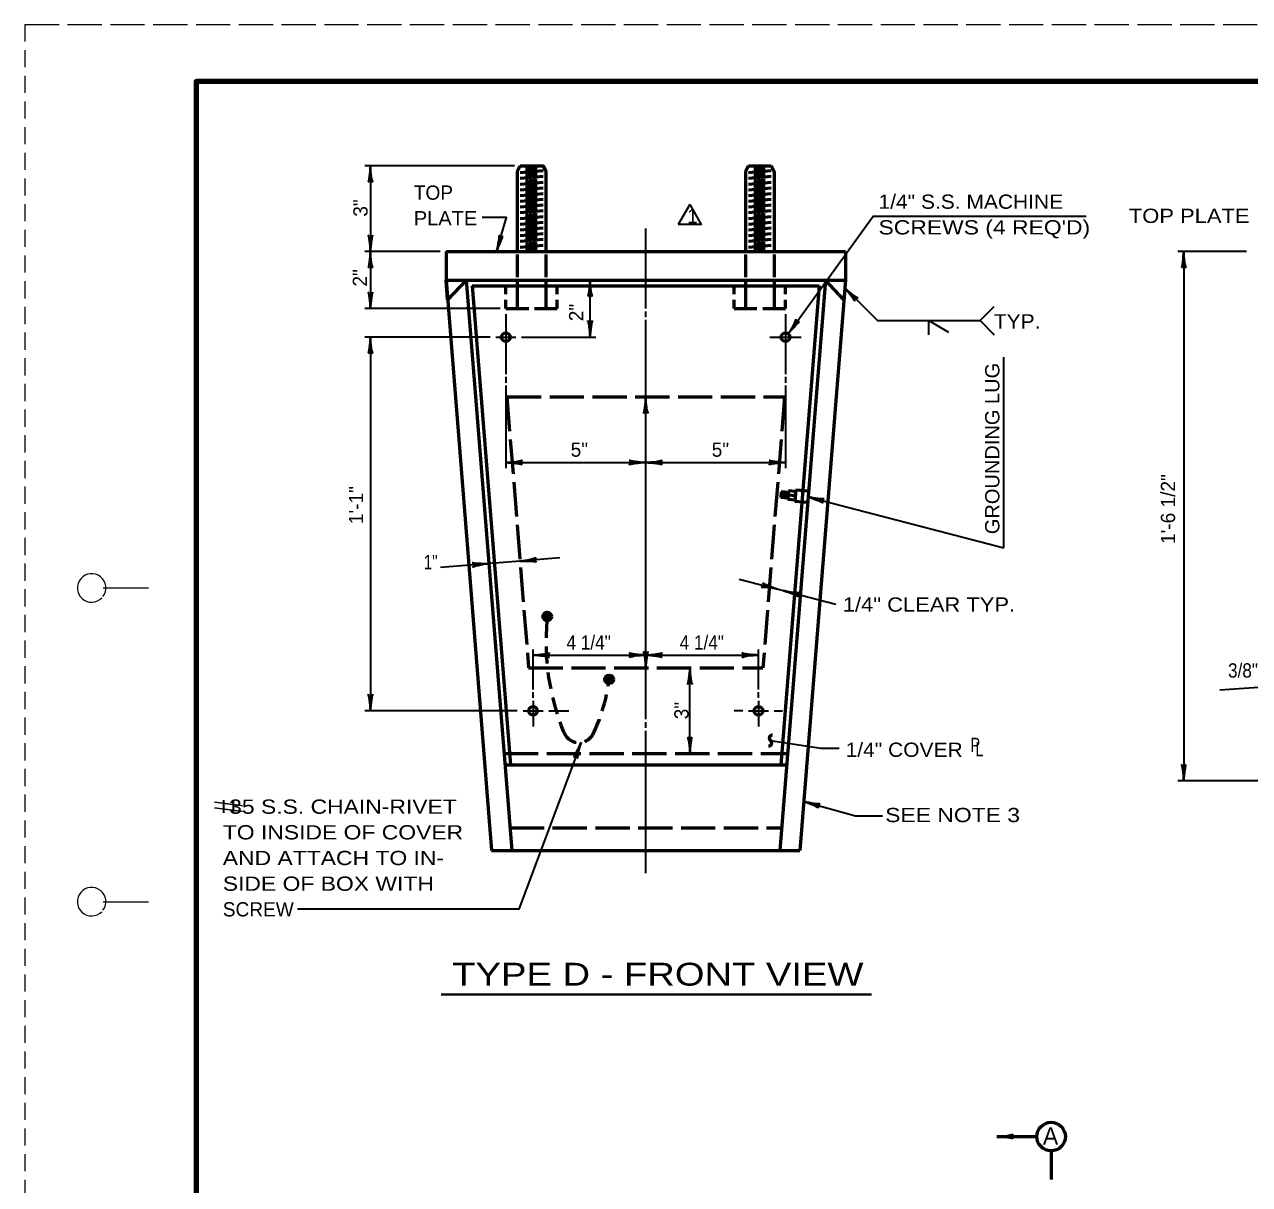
# Model space of a CAD drawing. Extents: x -1 to 679, y 0 to 440.
# Drawn here: x -1.1 to 213.6, y 236.4 to 439.8 of the extents above; entities that cross this region are included whole.
import ezdxf

# ---------------------------------------------------------------- set-up
doc = ezdxf.new("R2010")
doc.units = 0
doc.linetypes.add('LONG_DASHED', pattern=[7.5, 6, -1.5])
doc.linetypes.add('MEDIUM_DASHED', pattern=[4.5, 3, -1.5])
doc.layers.add('1', color=7, linetype='Continuous', lineweight=35)
doc.layers.add('61', color=7, linetype='Continuous', lineweight=35)

msp = doc.modelspace()

# ---------------------------------------------------------------- hatches: boundary and pattern name
at = {"layer": '1'}
for points in [[(91.319, 335.992, 1), (89.819, 335.992, 1)], [(102.185, 324.992, 1), (100.685, 324.992, 1)]]:
    msp.add_hatch(color=256, dxfattribs=at).paths.add_polyline_path(points)

# ---------------------------------------------------------------- linework, layer by layer
at = {"layer": '1', "linetype": 'MEDIUM_DASHED', "lineweight": 13}
msp.add_line((-0.995, 439.78), (-1.055, -0.26), dxfattribs=at)
at = {"layer": '1'}
for p, q in [((84.82, 414.992), (58.57, 414.992)), ((115.531, 408.207), (113.531, 404.743)), ((107.82, 389.992), (107.82, 403.992)), ((71.82, 399.992), (58.57, 399.992)), ((213.108, 399.992), (201.108, 399.992)), ((202.108, 399.992), (202.108, 307.218)), ((98.07, 384.992), (98.07, 394.992)), ((82.32, 389.992), (58.57, 389.992)), ((83.32, 388.992), (83.32, 378.492)), ((107.82, 388.492), (107.82, 389.492)), ((132.321, 388.992), (132.321, 378.492)), ((107.82, 374.492), (107.82, 387.992)), ((166.43, 387.873), (168.905, 385.398)), ((80.57, 384.992), (58.57, 384.992)), ((59.57, 384.992), (59.57, 319.492)), ((86.07, 384.992), (99.07, 384.992)), ((129.571, 384.992), (135.07, 384.992)), ((170.607, 348.058), (170.607, 381.474)), ((83.32, 377.992), (83.32, 376.992)), ((132.321, 377.992), (132.321, 376.992)), ((83.32, 376.492), (83.32, 361.992)), ((132.321, 376.492), (132.321, 361.992)), ((136.216, 357), (170.607, 348.058)), ((88.07, 323.242), (88.07, 330.242)), ((127.57, 323.242), (127.57, 330.242)), ((115.57, 311.992), (115.57, 326.992)), ((88.07, 321.742), (88.07, 322.742)), ((127.57, 321.742), (127.57, 322.742)), ((208.456, 323.135), (219.429, 323.902)), ((88.07, 321.242), (88.07, 316.742)), ((127.57, 321.242), (127.57, 316.742)), ((85.32, 319.492), (58.57, 319.492)), ((86.32, 319.492), (89.82, 319.492)), ((90.82, 319.492), (94.32, 319.492)), ((124.82, 319.492), (123.32, 319.492)), ((125.82, 319.492), (129.321, 319.492)), ((130.321, 319.492), (131.821, 319.492)), ((107.82, 316.492), (107.82, 317.492)), ((107.82, 290.992), (107.82, 315.992)), ((219.596, 307.218), (201.108, 307.218))]:
    msp.add_line(p, q, dxfattribs=at)
at = {"layer": '1', "lineweight": 53}
for p, q in [((85.82, 414.992), (85.32, 413.992)), ((86.773, 414.411), (88.781, 414.587)), ((125.82, 414.992), (125.32, 413.992)), ((125.82, 414.992), (129.821, 414.992)), ((126.773, 414.411), (128.781, 414.587)), ((129.821, 414.992), (130.321, 413.992)), ((85.32, 413.992), (85.32, 399.992)), ((85.82, 413.826), (89.82, 414.176)), ((85.82, 412.822), (89.82, 413.172)), ((86.773, 413.408), (88.781, 413.583)), ((86.773, 412.404), (88.781, 412.579)), ((90.32, 413.992), (90.32, 399.992)), ((125.32, 413.992), (125.32, 399.992)), ((125.82, 413.826), (129.821, 414.176)), ((125.82, 412.822), (129.821, 413.172)), ((126.773, 413.408), (128.781, 413.583)), ((126.773, 412.404), (128.781, 412.579)), ((130.321, 413.992), (130.321, 399.992)), ((85.82, 411.819), (89.82, 412.169)), ((85.82, 410.815), (89.82, 411.165)), ((85.82, 409.811), (89.82, 410.161)), ((86.773, 411.4), (88.781, 411.576)), ((86.773, 410.396), (88.781, 410.572)), ((125.82, 411.819), (129.821, 412.169)), ((125.82, 410.815), (129.821, 411.165)), ((125.82, 409.811), (129.821, 410.161)), ((126.773, 411.4), (128.781, 411.576)), ((126.773, 410.396), (128.781, 410.572)), ((85.82, 408.807), (89.82, 409.157)), ((85.82, 407.803), (89.82, 408.153)), ((86.773, 409.392), (88.781, 409.568)), ((86.773, 408.388), (88.781, 408.564)), ((125.82, 408.807), (129.821, 409.157)), ((125.82, 407.803), (129.821, 408.153)), ((126.773, 409.392), (128.781, 409.568)), ((126.773, 408.388), (128.781, 408.564)), ((85.82, 406.799), (89.82, 407.149)), ((85.82, 405.796), (89.82, 406.146)), ((86.773, 407.385), (88.781, 407.56)), ((86.773, 406.381), (88.781, 406.557)), ((125.82, 406.799), (129.821, 407.149)), ((125.82, 405.796), (129.821, 406.146)), ((126.773, 407.385), (128.781, 407.56)), ((126.773, 406.381), (128.781, 406.557)), ((85.82, 404.792), (89.82, 405.142)), ((85.82, 403.788), (89.82, 404.138)), ((86.773, 405.377), (88.781, 405.553)), ((86.773, 404.373), (88.781, 404.549)), ((125.82, 404.792), (129.821, 405.142)), ((125.82, 403.788), (129.821, 404.138)), ((126.773, 405.377), (128.781, 405.553)), ((126.773, 404.373), (128.781, 404.549)), ((85.82, 402.784), (89.82, 403.134)), ((85.82, 401.78), (89.82, 402.13)), ((86.773, 403.369), (88.781, 403.545)), ((86.773, 402.365), (88.781, 402.541)), ((86.773, 401.362), (88.781, 401.537)), ((125.82, 402.784), (129.821, 403.134)), ((125.82, 401.78), (129.821, 402.13)), ((126.773, 403.369), (128.781, 403.545)), ((126.773, 402.365), (128.781, 402.541)), ((126.773, 401.362), (128.781, 401.537)), ((72.82, 399.992), (142.82, 399.992)), ((72.82, 399.992), (72.82, 394.992)), ((85.32, 399.492), (85.32, 395.492)), ((85.82, 400.777), (89.82, 401.126)), ((86.773, 400.358), (88.781, 400.534)), ((90.32, 399.492), (90.32, 395.492)), ((125.32, 399.492), (125.32, 395.492)), ((125.82, 400.777), (129.821, 401.126)), ((126.773, 400.358), (128.781, 400.534)), ((130.321, 399.492), (130.321, 395.492)), ((142.82, 399.992), (142.82, 394.992)), ((72.82, 394.992), (142.82, 394.992)), ((72.821, 394.992), (80.82, 294.992)), ((76.332, 394.992), (84.332, 294.992)), ((77.415, 393.992), (84.135, 309.992)), ((77.415, 393.992), (138.226, 393.992)), ((83.32, 392.492), (83.32, 393.992)), ((85.32, 394.992), (85.32, 389.992)), ((90.32, 394.992), (90.32, 389.992)), ((92.32, 392.492), (92.32, 393.992)), ((123.32, 392.492), (123.32, 393.992)), ((125.32, 394.992), (125.32, 389.992)), ((130.321, 394.992), (130.321, 389.992)), ((139.309, 394.992), (131.309, 294.992)), ((138.226, 393.992), (131.506, 309.992)), ((132.321, 392.492), (132.321, 393.992)), ((142.82, 394.992), (134.82, 294.992)), ((83.32, 389.992), (83.32, 391.492)), ((92.32, 389.992), (92.32, 391.492)), ((123.32, 389.992), (123.32, 391.492)), ((132.321, 389.992), (132.321, 391.492)), ((83.32, 389.992), (87.32, 389.992)), ((88.32, 389.992), (92.32, 389.992)), ((123.32, 389.992), (127.32, 389.992)), ((128.321, 389.992), (132.321, 389.992)), ((131.575, 357.872), (131.495, 356.875)), ((132.741, 356.776), (131.495, 356.875)), ((132.82, 357.772), (131.575, 357.872)), ((131.772, 357.605), (131.732, 357.107)), ((131.988, 357.839), (131.908, 356.842)), ((132.195, 357.572), (132.155, 357.073)), ((132.4, 357.806), (132.321, 356.809)), ((132.621, 357.537), (132.581, 357.039)), ((132.84, 358.022), (132.721, 356.526)), ((133.967, 356.427), (132.721, 356.526)), ((134.027, 357.174), (132.781, 357.274)), ((134.087, 357.922), (132.84, 358.022)), ((134.106, 358.171), (133.947, 356.178)), ((136.349, 357.992), (134.106, 358.171)), ((136.19, 355.998), (133.947, 356.178)), ((83.132, 309.992), (132.509, 309.992)), ((80.82, 294.992), (134.82, 294.992)), ((169.37, 244.85), (176.37, 244.85)), ((178.87, 242.35), (178.87, 237.35))]:
    msp.add_line(p, q, dxfattribs=at)
at = {"layer": '1', "linetype": 'LONG_DASHED', "lineweight": 53}
for p, q in [((83.489, 374.492), (132.152, 374.492)), ((83.489, 374.492), (87.289, 326.992)), ((132.152, 374.492), (128.352, 326.992)), ((87.289, 326.992), (128.352, 326.992)), ((82.972, 311.992), (132.669, 311.992)), ((84.012, 298.992), (131.629, 298.992))]:
    msp.add_line(p, q, dxfattribs=at)
at = {"layer": '1', "lineweight": 40}
msp.add_line((71.944, 269.731), (147.413, 269.731), dxfattribs=at)
at = {"layer": '1'}
for points in [[(59.57, 414.992), (59.57, 399.992), (59.57, 389.992)], [(115.531, 408.207), (117.531, 404.743), (113.531, 404.743)], [(81.679, 399.992), (83.407, 405.946), (79.151, 405.946)], [(132.803, 385.566), (147.675, 406.201), (184.997, 406.201)], [(142.709, 393.595), (148.43, 387.873), (166.43, 387.873), (168.905, 390.348)], [(157.43, 385.373), (157.43, 387.873), (160.894, 385.873)], [(81.57, 384.992), (82.57, 384.992), (84.07, 384.992), (85.07, 384.992)], [(107.82, 317.992), (107.82, 326.992), (107.82, 374.492)], [(83.32, 362.992), (107.82, 362.992), (132.321, 362.992)], [(92.769, 346.268), (85.792, 345.709), (71.837, 344.593)], [(124.195, 342.56), (130.97, 340.798), (131.938, 340.547), (141.132, 338.156)], [(88.07, 329.242), (107.82, 329.242), (127.57, 329.242)], [(96.508, 313.95), (85.581, 284.709), (46.773, 284.709)], [(129.696, 314.254), (138.498, 312.907), (141.707, 312.907)], [(135.508, 303.585), (144.618, 301.093), (149.316, 301.093)]]:
    msp.add_lwpolyline(points, dxfattribs=at)
at = {"layer": '1', "lineweight": 53}
msp.add_lwpolyline([(85.82, 414.992), (89.82, 414.992), (90.32, 413.992)], dxfattribs=at)
for points in [[(73.1, 391.503), (72.82, 394.992), (76.332, 394.992), (73.1, 391.503)], [(139.309, 394.992), (142.82, 394.992), (142.541, 391.503)]]:
    msp.add_lwpolyline(points, close=True, dxfattribs=at)
for centre, radius in [((83.32, 384.992), 0.75), ((132.321, 384.992), 0.75), ((90.569, 335.992), 0.75), ((101.435, 324.992), 0.75), ((88.07, 319.492), 0.75), ((127.57, 319.492), 0.75), ((178.87, 244.85), 2.5)]:
    msp.add_circle(centre, radius, dxfattribs=at)
at = {"layer": '1', "linetype": 'MEDIUM_DASHED', "lineweight": 53}
for centre, radius, start, end in [((132.326, 331.569), 41.983, 174.97679, 202.08241), ((71.312, 328.629), 30.32, 333.87309, 351.69814), ((96.103, 316.78), 2.859, 200.36157, 328.28934)]:
    msp.add_arc(centre, radius, start, end, dxfattribs=at)
at = {"layer": '1', "lineweight": 53}
for centre, start, end in [((129.412, 313.828), 261.71531, 56.28469), ((129.981, 314.681), 81.71531, 236.28469)]:
    msp.add_arc(centre, 0.513, start, end, dxfattribs=at)
at = {"layer": '1', "lineweight": 40}
for centre, major_axis, ratio, start_param, end_param in [((59.359, 413.871), (0.176, 1.756), 0.07063, 3.1407148, 5.41811), ((59.359, 413.871), (0.176, 1.756), 0.07063, 3.1407148, 5.41811), ((59.847, 413.901), (-0.156, 1.786), 0.122415, 0.8963533, 3.1415927), ((59.847, 413.901), (-0.156, 1.786), 0.122415, 0.8963533, 3.1415927), ((59.294, 401.083), (0.156, -1.786), 0.122415, 0.8963533, 3.1415927), ((59.294, 401.083), (0.156, -1.786), 0.122415, 0.8963533, 3.1415927), ((59.782, 401.112), (-0.176, -1.756), 0.07063, 3.1407148, 5.41811), ((59.782, 401.112), (-0.176, -1.756), 0.07063, 3.1407148, 5.41811), ((81.717, 401.117), (-0.348, -1.758), 0.122415, 0.8963533, 3.1415927), ((82.194, 401.009), (0.658, 1.638), 0.07063, 6.2823074, 8.5597026), ((59.359, 398.871), (0.176, 1.756), 0.07063, 3.1407148, 5.41811), ((59.359, 398.871), (0.176, 1.756), 0.07063, 3.1407148, 5.41811), ((59.847, 398.901), (-0.156, 1.786), 0.122415, 0.8963533, 3.1415927), ((59.847, 398.901), (-0.156, 1.786), 0.122415, 0.8963533, 3.1415927), ((201.897, 398.871), (0.176, 1.756), 0.07063, 3.1407148, 5.41811), ((202.385, 398.901), (-0.156, 1.786), 0.122415, 0.8963533, 3.1415927), ((97.859, 393.871), (0.176, 1.756), 0.07063, 3.1407148, 5.41811), ((98.347, 393.901), (-0.156, 1.786), 0.122415, 0.8963533, 3.1415927), ((143.351, 392.653), (1.118, -1.366), 0.07063, 6.2823074, 8.5597026), ((143.351, 392.653), (1.118, -1.366), 0.07063, 6.2823074, 8.5597026), ((143.676, 393.019), (-1.373, 1.152), 0.122415, 0.8963533, 3.1415927), ((143.676, 393.019), (-1.373, 1.152), 0.122415, 0.8963533, 3.1415927), ((59.294, 391.083), (0.156, -1.786), 0.122415, 0.8963533, 3.1415927), ((59.294, 391.083), (0.156, -1.786), 0.122415, 0.8963533, 3.1415927), ((59.782, 391.112), (-0.176, -1.756), 0.07063, 3.1407148, 5.41811), ((59.782, 391.112), (-0.176, -1.756), 0.07063, 3.1407148, 5.41811), ((97.794, 386.083), (0.156, -1.786), 0.122415, 0.8963533, 3.1415927), ((98.282, 386.112), (-0.176, -1.756), 0.07063, 3.1407148, 5.41811), ((133.217, 386.613), (-0.917, -1.54), 0.122415, 0.8963533, 3.1415927), ((133.629, 386.352), (1.17, 1.322), 0.07063, 6.2823074, 8.5597026), ((59.359, 383.871), (0.176, 1.756), 0.07063, 3.1407148, 5.41811), ((59.847, 383.901), (-0.156, 1.786), 0.122415, 0.8963533, 3.1415927), ((107.609, 373.371), (0.176, 1.756), 0.07063, 3.1407148, 5.41811), ((108.097, 373.401), (-0.156, 1.786), 0.122415, 0.8963533, 3.1415927), ((84.441, 362.78), (-1.756, 0.176), 0.07063, 3.1407148, 5.41811), ((84.412, 363.268), (-1.786, -0.156), 0.122415, 0.8963533, 3.1415927), ((106.729, 362.715), (1.786, 0.156), 0.122415, 0.8963533, 3.1415927), ((106.729, 362.715), (1.786, 0.156), 0.122415, 0.8963533, 3.1415927), ((106.7, 363.203), (1.756, -0.176), 0.07063, 3.1407148, 5.41811), ((106.7, 363.203), (1.756, -0.176), 0.07063, 3.1407148, 5.41811), ((108.941, 362.78), (-1.756, 0.176), 0.07063, 3.1407148, 5.41811), ((108.941, 362.78), (-1.756, 0.176), 0.07063, 3.1407148, 5.41811), ((108.912, 363.268), (-1.786, -0.156), 0.122415, 0.8963533, 3.1415927), ((108.912, 363.268), (-1.786, -0.156), 0.122415, 0.8963533, 3.1415927), ((131.229, 362.715), (1.786, 0.156), 0.122415, 0.8963533, 3.1415927), ((131.2, 363.203), (1.756, -0.176), 0.07063, 3.1407148, 5.41811), ((137.247, 356.513), (-1.656, 0.612), 0.07063, 3.1407148, 5.41811), ((137.342, 356.993), (-1.768, 0.298), 0.122415, 0.8963533, 3.1415927), ((86.857, 346.072), (-1.768, -0.298), 0.122415, 0.8963533, 3.1415927), ((86.857, 346.072), (-1.768, -0.298), 0.122415, 0.8963533, 3.1415927), ((86.925, 345.588), (-1.765, 0.035), 0.07063, 3.1407148, 5.41811), ((86.925, 345.588), (-1.765, 0.035), 0.07063, 3.1407148, 5.41811), ((79.176, 345.392), (-1.765, 0.035), 0.07063, 6.2823074, 8.5597026), ((79.244, 344.908), (1.768, 0.298), 0.122415, 0.8963533, 3.1415927), ((129.939, 341.285), (-1.656, 0.612), 0.07063, 6.2823074, 8.5597026), ((129.939, 341.285), (-1.656, 0.612), 0.07063, 6.2823074, 8.5597026), ((129.845, 340.806), (1.768, -0.298), 0.122415, 0.8963533, 3.1415927), ((129.845, 340.806), (1.768, -0.298), 0.122415, 0.8963533, 3.1415927), ((132.969, 340.06), (1.656, -0.612), 0.07063, 6.2823074, 8.5597026), ((133.064, 340.54), (-1.768, 0.298), 0.122415, 0.8963533, 3.1415927), ((89.191, 329.03), (-1.756, 0.176), 0.07063, 3.1407148, 5.41811), ((89.191, 329.03), (-1.756, 0.176), 0.07063, 3.1407148, 5.41811), ((89.162, 329.518), (-1.786, -0.156), 0.122415, 0.8963533, 3.1415927), ((89.162, 329.518), (-1.786, -0.156), 0.122415, 0.8963533, 3.1415927), ((106.729, 328.965), (1.786, 0.156), 0.122415, 0.8963533, 3.1415927), ((106.7, 329.453), (1.756, -0.176), 0.07063, 3.1407148, 5.41811), ((107.544, 328.083), (0.156, -1.786), 0.122415, 0.8963533, 3.1415927), ((108.941, 329.03), (-1.756, 0.176), 0.07063, 3.1407148, 5.41811), ((108.941, 329.03), (-1.756, 0.176), 0.07063, 3.1407148, 5.41811), ((108.912, 329.518), (-1.786, -0.156), 0.122415, 0.8963533, 3.1415927), ((108.912, 329.518), (-1.786, -0.156), 0.122415, 0.8963533, 3.1415927), ((108.032, 328.112), (-0.176, -1.756), 0.07063, 3.1407148, 5.41811), ((126.479, 328.965), (1.786, 0.156), 0.122415, 0.8963533, 3.1415927), ((126.479, 328.965), (1.786, 0.156), 0.122415, 0.8963533, 3.1415927), ((126.45, 329.453), (1.756, -0.176), 0.07063, 3.1407148, 5.41811), ((126.45, 329.453), (1.756, -0.176), 0.07063, 3.1407148, 5.41811), ((115.359, 325.871), (0.176, 1.756), 0.07063, 3.1407148, 5.41811), ((115.847, 325.901), (-0.156, 1.786), 0.122415, 0.8963533, 3.1415927), ((59.294, 320.583), (0.156, -1.786), 0.122415, 0.8963533, 3.1415927), ((59.782, 320.612), (-0.176, -1.756), 0.07063, 3.1407148, 5.41811), ((95.917, 312.975), (0.779, 1.584), 0.07063, 3.1407148, 5.41811), ((96.384, 312.831), (0.479, 1.727), 0.122415, 0.8963533, 3.1415927), ((115.294, 313.083), (0.156, -1.786), 0.122415, 0.8963533, 3.1415927), ((115.782, 313.112), (-0.176, -1.756), 0.07063, 3.1407148, 5.41811), ((201.832, 308.31), (0.156, -1.786), 0.122415, 0.8963533, 3.1415927), ((202.32, 308.339), (-0.176, -1.756), 0.07063, 3.1407148, 5.41811), ((136.533, 303.085), (-1.648, 0.633), 0.07063, 3.1407148, 5.41811), ((136.533, 303.085), (-1.648, 0.633), 0.07063, 3.1407148, 5.41811), ((136.633, 303.563), (-1.764, 0.32), 0.122415, 0.8963533, 3.1415927), ((136.633, 303.563), (-1.764, 0.32), 0.122415, 0.8963533, 3.1415927), ((170.491, 244.639), (-1.756, 0.176), 0.07063, 3.1407148, 5.41811), ((170.462, 245.127), (-1.786, -0.156), 0.122415, 0.8963533, 3.1415927)]:
    msp.add_ellipse(centre, major_axis=major_axis, ratio=ratio, start_param=start_param, end_param=end_param, dxfattribs=at)
at = {"layer": '61', "linetype": 'LONG_DASHED', "lineweight": 13}
msp.add_line((-0.995, 439.78), (679.025, 439.78), dxfattribs=at)
at = {"layer": '61', "lineweight": 13}
for p, q in [((12.725, 341.02), (20.705, 341.04)), ((12.705, 286.02), (20.705, 286.02))]:
    msp.add_line(p, q, dxfattribs=at)
at = {"layer": '61', "lineweight": 158}
msp.add_lwpolyline([(668.045, 429.78), (29.005, 429.78), (29.005, 9.76)], dxfattribs=at)
at = {"layer": '61', "lineweight": 13}
for centre, end in [((10.703, 341.021), 316.23216), ((10.703, 286.021), 315.37577)]:
    msp.add_arc(centre, 2.5, 323.13009, end, dxfattribs=at)

# ---------------------------------------------------------------- texts
at = {"layer": '1'}
for s, height, p in [('TOP', 2.5, (67.177, 409.067)), ('1', 2.5, (115.079, 404.945)), ('5"', 2.5, (94.666, 364.009)), ('5"', 2.5, (119.388, 364.009)), ('SCREW', 2.5, (33.698, 283.43)), ('A', 3, (177.436, 243.457))]:
    msp.add_text(s, height=height, dxfattribs=at).set_placement(p)
for s, height, width, p in [('1/4" S.S. MACHINE', 2.5, 1.1, (148.621, 407.477)), ('PLATE', 2.5, 1.05, (67.177, 404.567)), ('TOP PLATE', 2.5, 1.15, (192.5, 404.995)), ("SCREWS (4 REQ'D)", 2.5, 1.2, (148.621, 402.977)), ('TYP.', 2.5, 1.1, (168.832, 386.491)), ('1"', 2.5, 0.8, (68.906, 344.294)), ('1/4" CLEAR TYP.', 2.5, 1.15, (142.358, 336.858)), ('4 1/4"', 2.5, 0.9, (93.937, 330.212)), ('4 1/4"', 2.5, 0.9, (113.772, 330.212)), ('3/8"', 2.5, 0.9, (209.879, 325.308)), ('1/4" COVER', 2.5, 1.1, (142.855, 311.406)), ('P', 2.5, 0.75, (164.758, 312.258)), ('L', 2.5, 0.75, (165.61, 311.527)), (' 35 S.S. CHAIN-RIVET', 2.5, 1.2, (33.698, 301.43)), ('SEE NOTE 3', 2.5, 1.2, (149.791, 299.963)), ('TO INSIDE OF COVER', 2.5, 1.2, (33.698, 296.93)), ('AND ATTACH TO IN-', 2.5, 1.2, (33.698, 292.43)), ('SIDE OF BOX WITH', 2.5, 1.2, (33.698, 287.93)), ('TYPE D - FRONT VIEW', 4, 1.25, (73.919, 271.311))]:
    msp.add_text(s, height=height, dxfattribs=dict(at, width=width)).set_placement(p)
for s, p in [('3"', (59.077, 406.089)), ('2"', (58.979, 393.843)), ('2"', (96.88, 387.769)), ('1\'-6 1/2"', (200.61, 348.723)), ('1\'-1"', (58.293, 352.207)), ('3"', (115.333, 317.992))]:
    msp.add_text(s, height=2.5, rotation=90, dxfattribs=at).set_placement(p)
for s, height, width, p in [('GROUNDING LUG', 2.5, 1.05, (169.811, 350.436)), ('#', 5, 0.65, (37.189, 301.456))]:
    msp.add_text(s, height=height, rotation=90, dxfattribs=dict(at, width=width)).set_placement(p)

doc.saveas('drawing.dxf')
